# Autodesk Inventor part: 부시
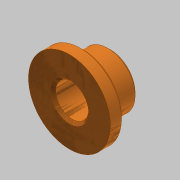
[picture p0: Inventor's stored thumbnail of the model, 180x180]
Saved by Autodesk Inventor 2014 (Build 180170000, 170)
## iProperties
Created: 2016-02
Part Number: 부시
Material: 스테인리스강
Document SubType Name: Modeling
Designer: mduedu
Density: 8.08 g/cm^3
Appearance: 금속 1600F 열
Mass: 39.4553 g
Surface Area: 27.3717 cm^2
Volume: 4.88308 cm^3
Author: mduedu
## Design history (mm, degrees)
sketch "스케치1"
  geometry: C1 r 15 at (0, 0); 1 further point
  constraints: 1 centre point, 1 coincident
  dimensions: "d0" = 30 diameter of C1
extrude "돌출1" new body sketch "스케치1" distance "d1" = 5; taper "d2" = 0 deg
sketch "스케치2"
  geometry: C1 r 10 at (0, 0); 1 further point
  constraints: 1 centre point, 1 coincident
  dimensions: "d3" = 20 diameter of C1
extrude "돌출2" join sketch "스케치2" distance "d4" = 10; taper "d5" = 0 deg
hole "구멍1" diameter "d8" = 12; stored, may be unused: countersink angle "d12" = 90 deg, drill point angle "d14" = 118 deg; dims "d9" = 6, "d10" = 4, "d11" = 2, "d13" = 8, "d15" = 10, "d16" = 10
chamfer "모따기1" distance "d17" = 1; stored, may be unused: second distance "d18" = 2, angle "d19" = 45 deg
chamfer "모따기2" distance "d20" = 1; stored, may be unused: second distance "d21" = 2, angle "d22" = 45 deg
chamfer "모따기3" distance "d23" = 1; stored, may be unused: second distance "d24" = 2, angle "d25" = 45 deg
node "솔리드1"
